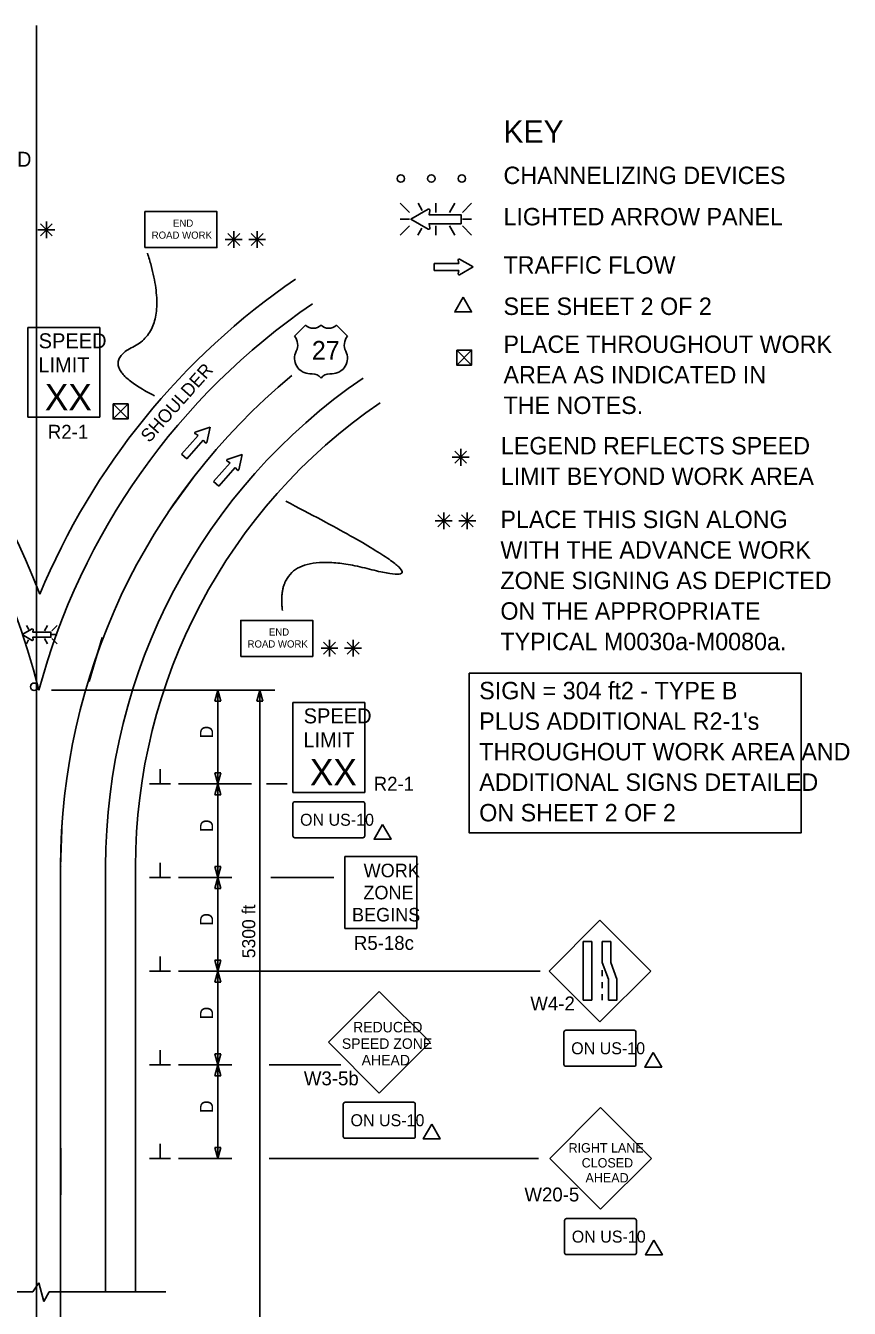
# Model space of a CAD drawing. Extents: x 16751 to 18479, y 5718 to 6974.
# Drawn here: x 16999 to 17439, y 6289 to 6974 of the extents above; entities that cross this region are included whole.
import ezdxf

# ---------------------------------------------------------------- set-up
doc = ezdxf.new("R2010")
doc.units = 0
for name, color, linetype in [('ALI_LEGAL_EX', 7, 'Continuous'), ('MT_SCRATCH_LEVEL_E', 7, 'Continuous'), ('PAVT_EDGE_EX', 7, 'Continuous'), ('TRAFFIC_SIGNS_PR', 7, 'Continuous'), ('TYPICAL_EX', 7, 'Continuous'), ('TYPICAL_TEXT_DIMEN_EX', 7, 'Continuous'), ('TYPICAL_TEXT_DIMEN_PR', 7, 'Continuous')]:
    doc.layers.add(name, color=color, linetype=linetype)

msp = doc.modelspace()

# ---------------------------------------------------------------- linework, layer by layer
at = {"layer": 'ALI_LEGAL_EX'}
for p, q in [((17004.68, 6974.12), (17004.68, 6155.98)), ((17004.68, 6877.04), (17004.68, 6013.12)), ((17039.84, 6647.53), (17032.85, 6623.88)), ((17017.65, 6024.8), (17017.65, 6525.15))]:
    msp.add_line(p, q, dxfattribs=at)
for points in [[(17004.68, 6949.12), (17004.68, 6974.12)], [(17075.14, 6714.42), (17089.89, 6734.61)], [(17017.7, 6524.8), (17017.65, 6525.15), (17018.48, 6549.78)], [(17017.65, 6424.8), (17017.65, 6449.8)], [(17017.7, 6349.8), (17017.7, 6374.8)]]:
    msp.add_lwpolyline(points, dxfattribs=at)
msp.add_arc((17357.65, 6525.15), 340, 129.56655, 180, dxfattribs=at)
at = {"layer": 'MT_SCRATCH_LEVEL_E'}
for p, q in [((17230.03, 6848.91), (17230.34, 6847.14)), ((17237.95, 6845.28), (17230.71, 6849.4)), ((17230.34, 6847.14), (17217.09, 6847.14)), ((17217.09, 6847.14), (17217.09, 6843.4)), ((17217.09, 6843.4), (17230.34, 6843.4)), ((17230.34, 6843.4), (17230.03, 6841.62)), ((17230.71, 6841.14), (17237.95, 6845.28)), ((17097.48, 6759.79), (17089.6, 6757.11)), ((17095.77, 6751.62), (17097.48, 6759.79)), ((17091.04, 6755.33), (17082.24, 6745.42)), ((17085.03, 6742.93), (17093.84, 6752.84)), ((17089.5, 6756.28), (17091.04, 6755.33)), ((17093.84, 6752.84), (17094.96, 6751.43)), ((17082.24, 6745.42), (17085.03, 6742.93)), ((17108.12, 6740.67), (17099.32, 6730.76)), ((17106.59, 6741.62), (17108.12, 6740.67)), ((17114.56, 6745.13), (17106.68, 6742.45)), ((17112.85, 6736.96), (17114.56, 6745.13)), ((17102.12, 6728.28), (17110.92, 6738.19)), ((17110.92, 6738.19), (17112.04, 6736.77)), ((17099.32, 6730.76), (17102.12, 6728.28))]:
    msp.add_line(p, q, dxfattribs=at)
for centre, start, end in [((17230.49, 6848.99), 60.42484, 189.96381), ((17230.49, 6841.55), 170.03619, 299.77312), ((17089.75, 6756.67), 108.80279, 238.34176), ((17095.31, 6751.73), 218.41415, 348.15107), ((17106.84, 6742.01), 108.80279, 238.34176), ((17112.4, 6737.07), 218.41415, 348.15107)]:
    msp.add_arc(centre, 0.463, start, end, dxfattribs=at)
at = {"layer": 'PAVT_EDGE_EX'}
for p, q in [((17041.65, 6525.15), (17041.65, 6298.02)), ((17057.65, 6525.15), (17057.65, 6298.02))]:
    msp.add_line(p, q, dxfattribs=at)
for centre, radius, start, end in [((16629.65, 6525.15), 404, 21.09612, 66.09058), ((16629.65, 6525.15), 388, 14.04823, 66.09058), ((17357.65, 6525.15), 380, 124.38118, 157.50106), ((17357.65, 6525.15), 364, 124.38118, 165.0045), ((17357.65, 6525.15), 316, 124.38117, 180), ((17357.65, 6525.15), 300, 124.38117, 180), ((17357.65, 6525.15), 300, 180, 180.00000277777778)]:
    msp.add_arc(centre, radius, start, end, dxfattribs=at)
at = {"layer": 'TRAFFIC_SIGNS_PR'}
for p, q in [((17199.02, 6879.29), (17203.95, 6874.36)), ((17210.78, 6875.47), (17208.57, 6879.3)), ((17218.1, 6874.36), (17218.1, 6879.3)), ((17225.34, 6874.36), (17228.19, 6879.3)), ((17232.25, 6874.36), (17237.19, 6879.3)), ((17203.95, 6870.8), (17199.02, 6870.8)), ((17232.25, 6870.8), (17237.19, 6870.8)), ((17199.02, 6862.32), (17203.95, 6867.25)), ((17208.53, 6862.31), (17210.64, 6865.98)), ((17218.1, 6867.25), (17218.1, 6862.31)), ((17228.23, 6862.31), (17225.38, 6867.25)), ((17232.25, 6867.25), (17237.19, 6862.31)), ((17000.14, 6813), (17038.54, 6813)), ((17000.14, 6765), (17000.14, 6813)), ((17038.54, 6765), (17038.54, 6813)), ((17000.14, 6765), (17038.54, 6765)), ((17000.64, 6651.64), (16999.38, 6653.82)), ((17004.82, 6651.01), (17004.82, 6653.82)), ((17008.96, 6651.01), (17010.59, 6653.82)), ((17012.91, 6651.01), (17015.73, 6653.83)), ((16999.35, 6644.12), (17000.56, 6646.21)), ((17004.82, 6646.94), (17004.82, 6644.12)), ((17010.61, 6644.12), (17008.98, 6646.94)), ((17012.91, 6648.97), (17015.73, 6648.97)), ((17012.91, 6646.94), (17015.73, 6644.12)), ((17141.7, 6612.74), (17180.1, 6612.74)), ((17141.7, 6564.74), (17141.7, 6612.74)), ((17180.1, 6564.74), (17180.1, 6612.74)), ((17141.7, 6564.74), (17180.1, 6564.74)), ((17141.7, 6558.74), (17141.7, 6541.54)), ((17142.7, 6559.74), (17179.1, 6559.74)), ((17180.1, 6558.74), (17180.1, 6541.54)), ((17142.7, 6540.54), (17179.1, 6540.54)), ((17169.48, 6492.09), (17169.48, 6530.49)), ((17169.48, 6530.49), (17207.88, 6530.49)), ((17207.88, 6492.09), (17207.88, 6530.49)), ((17305.71, 6496.48), (17278.56, 6469.33)), ((17332.87, 6469.33), (17305.71, 6496.48)), ((17169.48, 6492.09), (17207.88, 6492.09)), ((17278.56, 6469.33), (17305.71, 6442.17)), ((17305.71, 6442.17), (17332.87, 6469.33)), ((17306.96, 6469.82), (17306.96, 6466.62)), ((17187.82, 6458.47), (17160.67, 6431.31)), ((17214.97, 6431.31), (17187.82, 6458.47)), ((17306.96, 6463.42), (17306.96, 6460.22)), ((17306.96, 6457.02), (17306.96, 6453.82)), ((17287.51, 6437.73), (17323.92, 6437.73)), ((17160.67, 6431.31), (17187.82, 6404.16)), ((17187.82, 6404.16), (17214.97, 6431.31)), ((17286.51, 6436.73), (17286.51, 6419.53)), ((17324.92, 6436.73), (17324.92, 6419.53)), ((17287.51, 6418.53), (17323.92, 6418.53)), ((17168.65, 6398.31), (17168.65, 6381.11)), ((17169.65, 6399.31), (17206.05, 6399.31)), ((17207.05, 6398.31), (17207.05, 6381.11)), ((17306.02, 6396.48), (17278.87, 6369.33)), ((17333.17, 6369.33), (17306.02, 6396.48)), ((17169.65, 6380.11), (17206.05, 6380.11)), ((17278.87, 6369.33), (17306.02, 6342.18)), ((17306.02, 6342.18), (17333.17, 6369.33)), ((17286.82, 6336.18), (17286.82, 6318.98)), ((17287.82, 6337.18), (17324.23, 6337.18)), ((17325.23, 6336.18), (17325.23, 6318.98)), ((17287.82, 6317.98), (17324.23, 6317.98))]:
    msp.add_line(p, q, dxfattribs=at)
for points in [[(17214.03, 6876.08), (17204.74, 6870.8), (17214.03, 6865.48)], [(17214.9, 6866.11), (17214.5, 6868.38), (17231.52, 6868.38), (17231.52, 6873.18), (17214.5, 6873.18), (17214.91, 6875.46)], [(17002.5, 6651.99), (16997.19, 6648.97), (17002.5, 6645.93)], [(17003, 6646.29), (17002.77, 6647.59), (17012.49, 6647.59), (17012.49, 6650.33), (17002.77, 6650.33), (17003, 6651.63)]]:
    msp.add_lwpolyline(points, dxfattribs=at)
for points in [[(17062.69, 6855.62), (17101.09, 6855.62), (17101.09, 6874.82), (17062.69, 6874.82)], [(17113.9, 6637.34), (17152.3, 6637.34), (17152.3, 6656.54), (17113.9, 6656.54)], [(17296.82, 6485.06), (17296.82, 6453.82), (17301.31, 6453.82), (17301.31, 6485.06)], [(17306.96, 6485.06), (17306.96, 6473.88), (17310.3, 6465), (17310.3, 6453.82), (17314.79, 6453.82), (17314.79, 6465), (17311.45, 6473.88), (17311.45, 6485.06)]]:
    msp.add_lwpolyline(points, close=True, dxfattribs=at)
for centre in [(17199.36, 6892.49), (17215.66, 6892.49), (17231.96, 6892.49), (17003.5, 6621.15)]:
    msp.add_circle(centre, 2, dxfattribs=at)
for centre, radius, start, end in [((17214.32, 6875.56), 0.598, 350.73078, 118.89165), ((17214.32, 6866.01), 0.597, 241.48329, 9.95933), ((17002.66, 6651.69), 0.341, 350.73078, 118.89165), ((17002.66, 6646.23), 0.341, 241.48329, 9.95933), ((17142.7, 6558.74), 1, 90, 180), ((17179.1, 6558.74), 1, 0, 90), ((17142.7, 6541.54), 1, 180, 270), ((17179.1, 6541.54), 1, 270, 0), ((17287.51, 6436.73), 1, 90, 180), ((17323.92, 6436.73), 1, 0, 90), ((17287.51, 6419.53), 1, 180, 270), ((17323.92, 6419.53), 1, 270, 0), ((17169.65, 6398.31), 1, 90, 180), ((17206.05, 6398.31), 1, 0, 90), ((17169.65, 6381.11), 1, 180, 270), ((17206.05, 6381.11), 1, 270, 0), ((17287.82, 6336.18), 1, 90, 180), ((17324.23, 6336.18), 1, 0, 90), ((17287.82, 6318.98), 1, 180, 270), ((17324.23, 6318.98), 1, 270, 0)]:
    msp.add_arc(centre, radius, start, end, dxfattribs=at)
at = {"layer": 'TYPICAL_EX'}
for p, q in [((17142.58, 6808.34), (17148.47, 6814.24)), ((17170.88, 6808.34), (17164.98, 6814.24)), ((17150.83, 6788.28), (17152, 6788.28)), ((17162.63, 6788.28), (17161.45, 6788.28))]:
    msp.add_line(p, q, dxfattribs=at)
for centre, radius, start, end in [((17152.6, 6818.53), 5.96, 226.14041, 313.85958), ((17160.86, 6818.53), 5.96, 226.14042, 313.85959), ((17136.99, 6803.62), 7.31, 333.09768, 40.19361), ((17176.46, 6803.62), 7.31, 139.80639, 206.90233), ((17150.84, 6796.53), 8.24, 152.6698, 269.90132), ((17162.62, 6796.53), 8.24, 270.09868, 27.3302), ((17152.02, 6782.38), 5.91, 37.1038, 90.13853), ((17161.44, 6782.38), 5.91, 89.86147, 142.8962)]:
    msp.add_arc(centre, radius, start, end, dxfattribs=at)
at = {"layer": 'TYPICAL_TEXT_DIMEN_EX'}
msp.add_lwpolyline([(17235.92, 6628.43), (17413.13, 6628.43), (17413.13, 6543.16), (17235.92, 6543.16)], close=True, dxfattribs=at)
at = {"layer": 'TYPICAL_TEXT_DIMEN_PR'}
for p, q in [((17010.02, 6865.11), (17010.02, 6869.57)), ((17010.02, 6865.11), (17005.49, 6865.11)), ((17006.83, 6868.3), (17013.21, 6861.92)), ((17013.21, 6868.3), (17006.83, 6861.92)), ((17010.02, 6865.11), (17013.21, 6865.11)), ((17010.02, 6865.11), (17014.5, 6865.11)), ((17010.02, 6865.11), (17010.02, 6860.61)), ((17106.92, 6863.18), (17113.3, 6856.8)), ((17113.3, 6863.18), (17106.92, 6856.8)), ((17110.11, 6859.99), (17110.11, 6864.45)), ((17119.48, 6863.18), (17125.85, 6856.8)), ((17125.85, 6863.18), (17119.48, 6856.8)), ((17122.67, 6859.99), (17122.67, 6864.45)), ((17110.11, 6859.99), (17105.58, 6859.99)), ((17110.11, 6859.99), (17113.3, 6859.99)), ((17110.11, 6859.99), (17114.59, 6859.99)), ((17110.11, 6859.99), (17110.11, 6855.49)), ((17122.67, 6859.99), (17118.13, 6859.99)), ((17122.67, 6859.99), (17125.85, 6859.99)), ((17122.67, 6859.99), (17127.14, 6859.99)), ((17122.67, 6859.99), (17122.67, 6855.49)), ((17229.19, 6800.9), (17237.19, 6792.9)), ((17229.19, 6792.9), (17237.19, 6800.9)), ((17045.67, 6764.12), (17053.67, 6772.12)), ((17045.68, 6772.12), (17053.67, 6764.12)), ((17228.14, 6746.86), (17234.52, 6740.48)), ((17234.52, 6746.86), (17228.14, 6740.48)), ((17231.33, 6743.67), (17231.33, 6748.13)), ((17231.33, 6743.67), (17226.8, 6743.67)), ((17231.33, 6743.67), (17234.52, 6743.67)), ((17231.33, 6743.67), (17235.81, 6743.67)), ((17231.33, 6743.67), (17231.33, 6739.17)), ((17219.14, 6712.99), (17225.51, 6706.61)), ((17225.51, 6712.99), (17219.14, 6706.61)), ((17222.33, 6709.8), (17222.33, 6714.25)), ((17231.69, 6712.99), (17238.07, 6706.61)), ((17238.07, 6712.99), (17231.69, 6706.61)), ((17234.88, 6709.8), (17234.88, 6714.25)), ((17222.33, 6709.8), (17217.79, 6709.8)), ((17222.33, 6709.8), (17225.51, 6709.8)), ((17222.33, 6709.8), (17226.8, 6709.8)), ((17222.33, 6709.8), (17222.33, 6705.3)), ((17234.88, 6709.8), (17230.35, 6709.8)), ((17234.88, 6709.8), (17238.07, 6709.8)), ((17234.88, 6709.8), (17239.36, 6709.8)), ((17234.88, 6709.8), (17234.88, 6705.3)), ((17158.13, 6644.9), (17164.51, 6638.53)), ((17164.51, 6644.9), (17158.13, 6638.53)), ((17161.32, 6641.72), (17161.32, 6646.17)), ((17170.69, 6644.9), (17177.06, 6638.53)), ((17177.06, 6644.9), (17170.69, 6638.53)), ((17173.87, 6641.72), (17173.87, 6646.17)), ((17161.32, 6641.72), (17156.79, 6641.72)), ((17161.32, 6641.72), (17164.51, 6641.72)), ((17161.32, 6641.72), (17165.8, 6641.72)), ((17161.32, 6641.72), (17161.32, 6637.22)), ((17173.87, 6641.72), (17169.34, 6641.72)), ((17173.87, 6641.72), (17177.06, 6641.72)), ((17173.87, 6641.72), (17178.35, 6641.72)), ((17173.87, 6641.72), (17173.87, 6637.22)), ((17012.72, 6619.33), (17106.65, 6619.33)), ((17132.09, 6619.33), (17060.95, 6619.33)), ((17100.08, 6613.47), (17101.65, 6619.33)), ((17101.65, 6619.33), (17103.22, 6613.47)), ((17101.65, 6619.33), (17101.65, 6569.33)), ((17122.44, 6613.47), (17124.01, 6619.33)), ((17124.01, 6619.33), (17124.01, 6235.65)), ((17124.01, 6619.33), (17125.58, 6613.47)), ((17101.65, 6613.47), (17100.08, 6613.47)), ((17103.22, 6613.47), (17101.65, 6613.47)), ((17124.01, 6613.47), (17122.44, 6613.47)), ((17125.58, 6613.47), (17124.01, 6613.47)), ((17070.77, 6569.33), (17070.77, 6577.11)), ((17101.65, 6569.33), (17100.08, 6575.19)), ((17100.08, 6575.19), (17101.65, 6575.19)), ((17101.65, 6575.19), (17103.22, 6575.19)), ((17103.22, 6575.19), (17101.65, 6569.33)), ((17076.4, 6569.33), (17065.15, 6569.33)), ((17080.65, 6569.33), (17119.67, 6569.33)), ((17100.08, 6563.47), (17101.65, 6569.33)), ((17101.65, 6569.33), (17101.65, 6519.33)), ((17101.65, 6569.33), (17103.22, 6563.47)), ((17127.63, 6569.33), (17138.66, 6569.33)), ((17101.65, 6563.47), (17100.08, 6563.47)), ((17103.22, 6563.47), (17101.65, 6563.47)), ((17070.77, 6519.33), (17070.77, 6527.11)), ((17101.65, 6519.33), (17100.08, 6525.19)), ((17100.08, 6525.19), (17101.65, 6525.19)), ((17101.65, 6525.19), (17103.22, 6525.19)), ((17103.22, 6525.19), (17101.65, 6519.33)), ((17076.4, 6519.33), (17065.15, 6519.33)), ((17080.65, 6519.33), (17109.05, 6519.33)), ((17100.08, 6513.47), (17101.65, 6519.33)), ((17101.65, 6513.47), (17100.08, 6513.47)), ((17101.65, 6519.33), (17101.65, 6469.33)), ((17101.65, 6519.33), (17103.22, 6513.47)), ((17103.22, 6513.47), (17101.65, 6513.47)), ((17129.98, 6519.33), (17163.5, 6519.33)), ((17070.77, 6469.33), (17070.77, 6477.11)), ((17101.65, 6469.33), (17100.08, 6475.19)), ((17100.08, 6475.19), (17101.65, 6475.19)), ((17101.65, 6475.19), (17103.22, 6475.19)), ((17103.22, 6475.19), (17101.65, 6469.33)), ((17076.4, 6469.33), (17065.15, 6469.33)), ((17080.65, 6469.33), (17273.87, 6469.33)), ((17100.08, 6463.47), (17101.65, 6469.33)), ((17101.65, 6469.33), (17101.65, 6419.33)), ((17101.65, 6469.33), (17103.22, 6463.47)), ((17101.65, 6463.47), (17100.08, 6463.47)), ((17103.22, 6463.47), (17101.65, 6463.47)), ((17070.77, 6419.33), (17070.77, 6427.11)), ((17101.65, 6419.33), (17100.08, 6425.19)), ((17100.08, 6425.19), (17101.65, 6425.19)), ((17101.65, 6425.19), (17103.22, 6425.19)), ((17103.22, 6425.19), (17101.65, 6419.33)), ((17076.4, 6419.33), (17065.15, 6419.33)), ((17080.65, 6419.33), (17109.05, 6419.33)), ((17100.08, 6413.47), (17101.65, 6419.33)), ((17101.65, 6419.33), (17101.65, 6369.33)), ((17101.65, 6419.33), (17103.22, 6413.47)), ((17129, 6419.33), (17167.23, 6419.33)), ((17101.65, 6413.47), (17100.08, 6413.47)), ((17103.22, 6413.47), (17101.65, 6413.47)), ((17070.77, 6369.33), (17070.77, 6377.11)), ((17076.4, 6369.33), (17065.15, 6369.33)), ((17080.65, 6369.33), (17109.05, 6369.33)), ((17101.65, 6369.33), (17100.08, 6375.19)), ((17100.08, 6375.19), (17101.65, 6375.19)), ((17101.65, 6375.19), (17103.22, 6375.19)), ((17103.22, 6375.19), (17101.65, 6369.33)), ((17272.88, 6369.33), (17129, 6369.33)), ((17005.97, 6302.82), (17002.72, 6298.02)), ((17008.71, 6292.88), (17005.97, 6302.82)), ((17002.72, 6298.02), (16936.78, 6298.02)), ((17011.46, 6298.02), (17008.71, 6292.88)), ((17073.79, 6298.02), (17011.46, 6298.02))]:
    msp.add_line(p, q, dxfattribs=at)
for points in [[(17232.66, 6829.11), (17228.14, 6821.28), (17237.19, 6821.28)], [(17229.19, 6800.9), (17229.19, 6792.9), (17237.19, 6792.9), (17237.19, 6800.9)], [(17045.68, 6772.12), (17045.67, 6764.12), (17053.67, 6764.12), (17053.67, 6772.12)], [(17189.65, 6547.6), (17185.12, 6539.77), (17194.17, 6539.77)], [(17334.21, 6425.91), (17329.69, 6418.07), (17338.74, 6418.07)], [(17215.85, 6387.56), (17211.32, 6379.73), (17220.37, 6379.73)], [(17334.53, 6325.75), (17330.01, 6317.92), (17339.06, 6317.92)]]:
    msp.add_lwpolyline(points, close=True, dxfattribs=at)
for points in [[(17067.74, 6776.56), (17035.79, 6792.58), (17076.97, 6812.63), (17064.02, 6852.67)], [(17138.01, 6720.2), (17233.21, 6670.88), (17131.63, 6697.14), (17136.1, 6661.91)]]:
    msp.add_open_spline(points, degree=2, dxfattribs=at)

# ---------------------------------------------------------------- texts
at = {"layer": 'TRAFFIC_SIGNS_PR'}
for s, height, p in [('SPEED', 8, (16965.8, 6898.79)), ('END', 3.831, (17077.69, 6866.75)), ('ROAD WORK', 3.831, (17066.3, 6860.36)), ('SPEED', 8, (17005.91, 6801.86)), ('PLACE THROUGHOUT WORK', 9.3, (17254.2, 6799.39)), ('LIMIT', 8, (17005.75, 6789.06)), ('AREA AS INDICATED IN', 9.3, (17254.2, 6783.09)), ('XX', 14.031, (17009.25, 6768.76)), ('THE NOTES.', 9.3, (17254.2, 6766.79)), ('R2-1', 7.44, (17010.82, 6753.56)), ('PLACE THIS SIGN ALONG', 9.3, (17252.56, 6705.87)), ('WITH THE ADVANCE WORK', 9.3, (17252.56, 6689.57)), ('ZONE SIGNING AS DEPICTED', 9.3, (17252.56, 6673.27)), ('ON THE APPROPRIATE', 9.3, (17252.56, 6656.97)), ('END', 3.831, (17128.9, 6648.47)), ('TYPICAL M0030a-M0080a.', 9.3, (17252.56, 6640.67)), ('ROAD WORK', 3.831, (17117.5, 6642.09)), ('SPEED', 8, (17147.47, 6601.6)), ('LIMIT', 8, (17147.3, 6588.8)), ('XX', 14.031, (17150.81, 6568.5)), ('R2-1', 7.44, (17184.87, 6565.65)), ('ON US-10', 6.4, (17145.54, 6546.94)), ('WORK', 7.217, (17179.48, 6519.46)), ('ZONE', 7.217, (17179.36, 6507.65)), ('BEGINS', 7.217, (17173.29, 6495.84)), ('R5-18c', 7.44, (17174.29, 6480.66)), ('W4-2', 7.441, (17268.53, 6448.32)), ('REDUCED', 5.6, (17173.88, 6436.62)), ('SPEED ZONE', 5.6, (17167.87, 6427.82)), ('ON US-10', 6.401, (17290.35, 6424.93)), ('AHEAD', 5.6, (17178.43, 6419.02)), ('W3-5b', 7.44, (17147.57, 6408.35)), ('ON US-10', 6.4, (17172.49, 6386.51)), ('RIGHT LANE', 4.999, (17288.97, 6372.48)), ('CLOSED', 4.999, (17295.96, 6364.48)), ('AHEAD', 4.999, (17298.01, 6356.49)), ('W20-5', 7.439, (17265.38, 6346.34)), ('ON US-10', 6.401, (17290.66, 6324.38))]:
    msp.add_text(s, height=height, dxfattribs=at).set_placement(p)
at = {"layer": 'TYPICAL_EX'}
msp.add_text('27', height=10, dxfattribs=at).set_placement((17151.84, 6795.77))
at = {"layer": 'TYPICAL_TEXT_DIMEN_EX'}
for s, height, p in [('KEY', 12, (17254.2, 6911.6)), ('CHANNELIZING DEVICES', 9.3, (17254.2, 6889.55)), ('LIGHTED ARROW PANEL', 9.3, (17254.2, 6867.5)), ('TRAFFIC FLOW', 9.3, (17254.2, 6841.7)), ('SEE SHEET 2 OF 2', 9.3, (17254.2, 6819.65)), ('LEGEND REFLECTS SPEED', 9.3, (17252.78, 6745.2)), ('LIMIT BEYOND WORK AREA', 9.3, (17252.78, 6728.9)), ('SIGN = 304 ft2 - TYPE B', 9.3, (17241.24, 6614.47)), ("PLUS ADDITIONAL R2-1's", 9.3, (17241.24, 6598.16)), ('THROUGHOUT WORK AREA AND', 9.3, (17241.24, 6581.86)), ('ADDITIONAL SIGNS DETAILED', 9.3, (17241.24, 6565.57)), ('ON SHEET 2 OF 2', 9.3, (17241.24, 6549.27))]:
    msp.add_text(s, height=height, dxfattribs=at).set_placement(p)
at = {"layer": 'TYPICAL_TEXT_DIMEN_PR'}
for s, rotation, p in [('SHOULDER', 48.37803, (17065, 6751.09)), ('D', 90, (17099.09, 6593.55)), ('D', 90, (17099.09, 6543.55)), ('D', 90, (17099.09, 6493.55)), ('5300 ft', 90, (17121.62, 6476.2)), ('D', 90, (17099.09, 6443.55)), ('D', 90, (17099.09, 6393.55))]:
    msp.add_text(s, height=7, rotation=rotation, dxfattribs=at).set_placement(p)

doc.saveas('drawing.dxf')
